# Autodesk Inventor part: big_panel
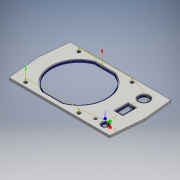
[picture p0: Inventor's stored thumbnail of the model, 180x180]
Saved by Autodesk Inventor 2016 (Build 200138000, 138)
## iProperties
Created: 2016-12
Part Number: big_panel
Material: Типовые
Document SubType Name: Modeling
Designer: admin
Density: 1 g/cm^3
Appearance: По умолчанию
Author: admin
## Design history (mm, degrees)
sketch "Эскиз1"
  geometry: L1 (-68, -41.5)-(68, -41.5); L2 (68, 41.5)-(-68, 41.5); L3 (-68, 41.5)-(-72, 2); L4 (-72, 2)-(-68, -41.5); L5 (68, 41.5)-(72, 2); L6 (72, 2)-(68, -41.5); 2 further points
  constraints: 12 end point, 1 horizontal, 1 midpoint, 1 parallel, 1 vertical alignment
extrude "Выдавливание1" new body sketch "Эскиз1" distance "d20" = 3; taper "d21" = 0 deg
sketch "Эскиз2"
  geometry: L1 (-55, -40)-(25, -40); L2 (25, -40)-(25, 40); L3 (25, 40)-(-55, 40); L4 (-55, 40)-(-55, -40); L5 (-55, -40)-(25, 40); L6 (25, -40)-(-55, 40); L7 (-51, -36)-(21, 36); L8 (21, -36)-(-51, 36); L9 (-68, 41.5)-(-72, 2) reference; L10 (-72, 2)-(-72, 44.842); L11 (-28.647, 36)-(-1.353, 36); L12 (-1.353, 36)-(-28.647, 36); L13 (-28.647, -36)-(-1.353, -36); C1 r 2.25 at (-51, 36); C2 r 2.25 at (21, 36); C3 r 2.25 at (-51, -36); C4 r 2.25 at (21, -36); A1 r 38.5 centre (-15, 0) between (-28.647, 36) and (-28.647, -36); A2 r 38.5 centre (-15, 0) between (-1.353, -36) and (-1.353, 36); 2 further points
  constraints: 24 end point, 6 centre point, 5 coincident, 4 midpoint, 4 point on circle, 2 horizontal, 2 parallel, 1 perpendicular, 1 vertical
  dimensions: "d26" = 80 distance of L3.end L2.end; "d27" = 80 distance of L2.end L1.end; "d28" = 72 distance of L8.end L7.end; "d29" = 72 distance of L7.end L8.start; "d30" = 4.5 diameter of C1; "d31" = 4.5 diameter of C2; "d32" = 4.5 diameter of C3; "d33" = 4.5 diameter of C4; "d35" = 17 distance between parallel lines of L10 L4
extrude "Выдавливание2" cut sketch "Эскиз2" distance "d36" = 10; taper "d37" = 0 deg
sketch "Эскиз3"
  geometry: L1 (40.5, 27.142)-(40.5, 22.858); L2 (68, -41.5)-(72, 2) reference; L3 (41.95, -9.6)-(54.05, -9.6); L4 (54.05, -9.6)-(54.05, 9.6); L5 (54.05, 9.6)-(41.95, 9.6); L6 (41.95, 9.6)-(41.95, -9.6); L7 (41.95, -9.6)-(54.05, 9.6); L8 (54.05, -9.6)-(41.95, 9.6); L9 (-68, -41.5)-(68, -41.5) reference; L10 (72, 2)-(72, -56.036); L11 (-72, 2)-(-68, -41.5) reference; L12 (-72, 2)-(-72, -53.21); C1 r 5.25 at (52, -31.5); C2 r 2 at (39, -31.5); A1 r 7.8 centre (48, 25) between (40.5, 22.858) and (40.5, 27.142); 4 further points
  constraints: 18 end point, 4 midpoint, 3 centre point, 3 vertical, 2 parallel, 2 point on circle, 1 horizontal, 1 perpendicular
  dimensions: "d38" = 15.6 diameter of A1; "d40" = 7.5 distance from line of A1.centre L1; "d41" = 48 horizontal distance of point (0, 0) A1.centre; "d42" = 25 vertical distance of point (0, 0) A1.centre; "d43" = 12.1 distance of L5.end L4.end; "d44" = 19.2 distance of L4.end L3.end; "d45" = 10.5 diameter of C1; "d46" = 4 diameter of C2; "d47" = 13 distance of C2.centre C1.centre; "d48" = 10 distance from line of L9 C1.centre; "d49" = 20 distance from line of L10 C1.centre; "d50" = 48 distance of point (0, 0) point (48, 0); "d53" = 52 horizontal distance of point (0, 0) C1.centre (derived)
extrude "Выдавливание3" cut sketch "Эскиз3" distance "d51" = 10; taper "d52" = 0 deg
node "Твердое тело1"
other parameters: "d34" = 77
